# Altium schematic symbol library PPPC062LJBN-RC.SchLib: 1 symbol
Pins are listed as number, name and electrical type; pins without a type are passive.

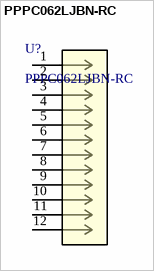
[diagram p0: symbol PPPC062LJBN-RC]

## PPPC062LJBN-RC
designator U?
Description; Manufacturer_Name: Sullins
footprint CONN_PPPC062LJBN-RC_SUL
pins: 1, 2, 3, 4, 5, 6, 7, 8, 9, 10, 11, 12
